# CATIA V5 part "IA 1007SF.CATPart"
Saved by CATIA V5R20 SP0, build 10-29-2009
Part number: IA 1007SF
Revision: ANY
Definition: UNKNOWN
Nomenclature: IA 1007SF
Source: Unknown
Bounding box of the stored display mesh (mm): x -5.35 to 5.35, y -17 to 0, z -5.35 to 5.35
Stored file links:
  C:\Users\Utente\Desktop\IO LAVORO\3D X SITO CF\CUMSA\3D files IA\IA 1007SF\IA 1007SF.CATPart
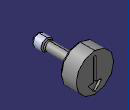
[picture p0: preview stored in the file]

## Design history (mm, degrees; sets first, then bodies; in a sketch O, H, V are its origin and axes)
Body1 "Cortar-Extruir1" (main body)
  Solid1: solid without history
